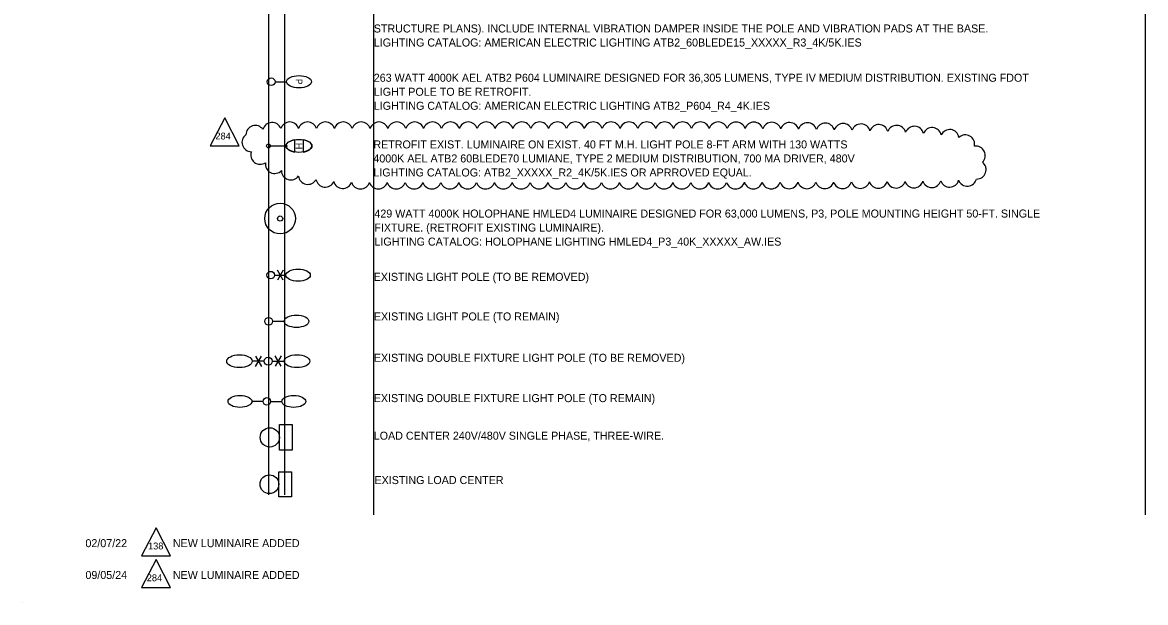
# Model space of a CAD drawing. Extents: x -0.6 to 15.1, y -0.9 to 9.2.
# Drawn here: x -0.55 to 9.27, y -0.9 to 4.17 of the extents above; entities that cross this region are included whole.
import ezdxf

# ---------------------------------------------------------------- set-up
doc = ezdxf.new("R2010")
doc.units = 0
for name, color, linetype in [('ActivePointCell_dp', 7, 'Continuous'), ('AdhocPoint_dp', 7, 'Continuous'), ('Cloud_dp', 7, 'Continuous'), ('LoadCenter', 7, 'Continuous'), ('LoadCenter_ep', 7, 'Continuous'), ('PoleLight', 7, 'Continuous'), ('PoleLight_ep', 7, 'Continuous'), ('TextLabel', 7, 'Continuous'), ('TextMisc', 7, 'Continuous')]:
    doc.layers.add(name, color=color, linetype=linetype)

msp = doc.modelspace()

# ---------------------------------------------------------------- linework, layer by layer
at = {"layer": 'ActivePointCell_dp'}
for p, q in [((2.5213, -0.1347), (2.5213, 8.8406)), ((9.2686, -0.1347), (9.2686, 8.9112)), ((1.7419, 8.8041), (1.7419, 0.0422)), ((1.6003, 8.6424), (1.6003, 0.0422))]:
    msp.add_line(p, q, dxfattribs=at)
at = {"layer": 'AdhocPoint_dp'}
msp.add_line((-0.55, -0.9), (-0.55, -0.9), dxfattribs=at)
at = {"layer": 'Cloud_dp'}
for points in [[(1.2182, 3.3362), (1.0915, 3.0921), (1.3449, 3.0921)], [(0.618, -0.2467), (0.4913, -0.4908), (0.7447, -0.4908)], [(0.618, -0.5247), (0.4913, -0.7688), (0.7447, -0.7688)]]:
    msp.add_lwpolyline(points, close=True, dxfattribs=at)
for centre, radius, start, end in [((1.4851, 3.188), 0.0818, 34.39181, 179.39181), ((1.6319, 3.2139), 0.0818, 20.63705, 165.63705), ((1.7865, 3.2181), 0.0818, 17.50167, 162.50167), ((1.9426, 3.2182), 0.0818, 17.5, 162.5), ((2.0987, 3.2182), 0.0818, 17.5, 162.5), ((2.2548, 3.2182), 0.0818, 17.5, 162.5), ((2.4109, 3.2182), 0.0818, 17.5, 162.5), ((2.567, 3.2182), 0.0818, 17.5, 162.5), ((2.7231, 3.2182), 0.0818, 17.50775, 162.50775), ((2.8792, 3.2182), 0.0818, 17.51566, 162.51566), ((3.0353, 3.2182), 0.0818, 17.51566, 162.51566), ((3.1914, 3.2183), 0.0818, 17.51566, 162.51566), ((3.3475, 3.2183), 0.0818, 17.51566, 162.51566), ((3.5036, 3.2184), 0.0818, 17.51566, 162.51566), ((3.6597, 3.2184), 0.0818, 17.51566, 162.51566), ((3.8158, 3.2184), 0.0818, 17.51566, 162.51566), ((3.9719, 3.2185), 0.0818, 17.51566, 162.51566), ((4.128, 3.2185), 0.0818, 17.51566, 162.51566), ((4.2841, 3.2186), 0.0818, 17.51566, 162.51566), ((4.4402, 3.2186), 0.0818, 17.51566, 162.51566), ((4.5963, 3.2187), 0.0818, 17.51566, 162.51566), ((4.7524, 3.2187), 0.0818, 17.51566, 162.51566), ((4.9085, 3.2187), 0.0818, 17.51566, 162.51566), ((5.0646, 3.2188), 0.0818, 17.51566, 162.51566), ((5.2207, 3.2188), 0.0818, 17.48665, 162.48665), ((5.3767, 3.2186), 0.0818, 17.39887, 162.39887), ((5.5328, 3.2182), 0.0818, 17.30058, 162.30058), ((5.6889, 3.2175), 0.0818, 17.19123, 162.19123), ((5.8449, 3.2165), 0.0818, 17.06859, 162.06859), ((6.0009, 3.2152), 0.0818, 16.92972, 161.92972), ((6.1569, 3.2134), 0.0818, 16.7707, 161.7707), ((6.3129, 3.2112), 0.0818, 16.58612, 161.58612), ((6.4689, 3.2084), 0.0818, 16.36832, 161.36832), ((6.6249, 3.2049), 0.0818, 16.10595, 161.10595), ((6.7808, 3.2007), 0.0818, 15.78139, 160.78139), ((6.9366, 3.1955), 0.0818, 15.36536, 160.36536), ((7.0923, 3.1889), 0.0818, 14.80475, 159.80475), ((7.2478, 3.1805), 0.0818, 13.98964, 158.98964), ((7.4029, 3.1691), 0.0818, 12.63875, 157.63875), ((1.4508, 3.1222), 0.0818, 125.49589, 270.49589), ((7.5567, 3.152), 0.0818, 9.63548, 154.63548), ((7.6929, 3.1055), 0.0818, 347.67382, 132.67382), ((7.7857, 3.0072), 0.0818, 314.04105, 99.04105), ((1.5281, 3.0117), 0.0818, 159.4718, 304.4718), ((7.7933, 2.8832), 0.0818, 267.88977, 52.88977), ((1.6553, 2.9318), 0.0818, 171.23593, 316.23593), ((1.7963, 2.875), 0.0818, 179.859, 324.859), ((1.9446, 2.8365), 0.0818, 186.09327, 331.09327), ((2.0965, 2.8126), 0.0818, 191.00451, 336.00451), ((2.2503, 2.8005), 0.0818, 195.00672, 340.00672), ((2.4053, 2.797), 0.0818, 197.41514, 342.41514), ((2.5614, 2.7969), 0.0818, 197.5, 342.5), ((2.7175, 2.7969), 0.0818, 197.5, 342.5), ((2.8736, 2.7969), 0.0818, 197.5, 342.5), ((3.0297, 2.7969), 0.0818, 197.5, 342.5), ((3.1858, 2.7969), 0.0818, 197.5, 342.5), ((3.3419, 2.7969), 0.0818, 197.5, 342.5), ((3.498, 2.7969), 0.0818, 197.5, 342.5), ((3.6541, 2.7969), 0.0818, 197.5, 342.5), ((3.8102, 2.7969), 0.0818, 197.5, 342.5), ((3.9663, 2.7969), 0.0818, 197.5, 342.5), ((4.1224, 2.7969), 0.0818, 197.5, 342.5), ((4.2785, 2.7969), 0.0818, 197.5, 342.5), ((4.4346, 2.7969), 0.0818, 197.5, 342.5), ((4.5907, 2.7969), 0.0818, 197.5, 342.5), ((4.7468, 2.7969), 0.0818, 197.5, 342.5), ((4.9029, 2.7969), 0.0818, 197.5, 342.5), ((5.059, 2.7969), 0.0818, 197.5, 342.5), ((5.2151, 2.7969), 0.0818, 197.50354, 342.50354), ((5.3711, 2.797), 0.0818, 197.52374, 342.52374), ((5.5272, 2.797), 0.0818, 197.54802, 342.54802), ((5.6833, 2.7972), 0.0818, 197.57496, 342.57496), ((5.8394, 2.7975), 0.0818, 197.60506, 342.60506), ((5.9955, 2.7978), 0.0818, 197.63901, 342.63901), ((6.1516, 2.7982), 0.0818, 197.67771, 342.67771), ((6.3076, 2.7988), 0.0818, 197.72236, 342.72236), ((6.4637, 2.7994), 0.0818, 197.77468, 342.77468), ((6.6198, 2.8003), 0.0818, 197.83715, 342.83715), ((6.7759, 2.8013), 0.0818, 197.91355, 342.91355), ((6.9319, 2.8026), 0.0818, 198.00998, 343.00998), ((7.0879, 2.8041), 0.0818, 198.13712, 343.13712), ((7.2439, 2.8061), 0.0818, 198.31582, 343.31582), ((7.3999, 2.8087), 0.0818, 198.5947, 343.5947), ((7.5557, 2.8124), 0.0818, 199.12998, 344.12998), ((7.7105, 2.8203), 0.0819, 201.69734, 346.69734)]:
    msp.add_arc(centre, radius, start, end, dxfattribs=at)
at = {"layer": 'LoadCenter'}
for p, q in [((1.6966, 0.431), (1.6966, 0.6559)), ((1.6966, 0.6559), (1.8091, 0.6559)), ((1.8091, 0.6559), (1.8091, 0.431)), ((1.8091, 0.431), (1.6966, 0.431))]:
    msp.add_line(p, q, dxfattribs=at)
msp.add_circle((1.6123, 0.5435), 0.0843, dxfattribs=at)
at = {"layer": 'LoadCenter_ep'}
for p, q in [((1.6911, 0.0243), (1.6911, 0.2436)), ((1.6911, 0.2436), (1.8008, 0.2436)), ((1.8008, 0.2436), (1.8008, 0.0243)), ((1.8008, 0.0243), (1.6911, 0.0243))]:
    msp.add_line(p, q, dxfattribs=at)
msp.add_circle((1.6089, 0.1339), 0.0822, dxfattribs=at)
at = {"layer": 'PoleLight'}
for p, q in [((1.6584, 3.6517), (1.7598, 3.6517)), ((1.8317, 3.0369), (1.8317, 3.1443)), ((1.9032, 3.1443), (1.9032, 3.0369)), ((1.5968, 3.0906), (1.7658, 3.0906))]:
    msp.add_line(p, q, dxfattribs=at)
for centre, radius in [((1.6246, 3.6517), 0.0338), ((1.6001, 3.0903), 0.0163), ((1.7026, 2.4559), 0.1344), ((1.7026, 2.4559), 0.0224)]:
    msp.add_circle(centre, radius, dxfattribs=at)
for centre, major_axis in [((1.8679, 3.6517), (0.1082, 0)), ((1.8674, 3.0906), (-0.1133, 0))]:
    msp.add_ellipse(centre, major_axis=major_axis, ratio=0.5, dxfattribs=at)
for start_param, end_param in [(5.033538, 6.283185), (1.891945, 4.391241), (0, 0.847605), (0.847605, 1.249648)]:
    msp.add_ellipse((1.8674, 3.0906), major_axis=(-0.1133, 0), ratio=0.5, start_param=start_param, end_param=end_param, dxfattribs=at)
at = {"layer": 'PoleLight_ep'}
for p, q in [((1.7285, 1.918), (1.6785, 2.0045)), ((1.7285, 2.0045), (1.6785, 1.918)), ((1.6535, 1.9613), (1.7534, 1.9613)), ((1.6363, 1.558), (1.7377, 1.558)), ((1.5636, 1.2092), (1.4589, 1.2092)), ((1.4861, 1.1633), (1.5385, 1.254)), ((1.4861, 1.254), (1.5385, 1.1633)), ((1.6334, 1.2092), (1.7381, 1.2092)), ((1.7109, 1.2551), (1.6586, 1.1645)), ((1.7109, 1.1645), (1.6586, 1.2551)), ((1.5539, 0.858), (1.456, 0.858)), ((1.6192, 0.858), (1.7171, 0.858))]:
    msp.add_line(p, q, dxfattribs=at)
for centre, radius in [((1.6202, 1.9613), 0.0333), ((1.6025, 1.558), 0.0338), ((1.5985, 1.2092), 0.0349), ((1.5866, 0.858), 0.0326)]:
    msp.add_circle(centre, radius, dxfattribs=at)
for centre, major_axis in [((1.86, 1.9613), (0.1066, 0)), ((1.8458, 1.558), (0.1082, 0)), ((1.3472, 1.2092), (-0.1117, 0)), ((1.8499, 1.2092), (0.1117, 0)), ((1.3515, 0.858), (-0.1045, 0)), ((1.8216, 0.858), (0.1045, 0))]:
    msp.add_ellipse(centre, major_axis=major_axis, ratio=0.5, dxfattribs=at)

# ---------------------------------------------------------------- texts
at = {"layer": 'Cloud_dp'}
for s, p in [('284', (1.1371, 3.1471)), ('138', (0.5481, -0.4358)), ('284', (0.5369, -0.7138))]:
    msp.add_text(s, height=0.05998, rotation=0, dxfattribs=at).set_placement(p)
at = {"layer": 'TextLabel'}
for s, p in [('P', (1.8393, 3.6775)), ('H', (1.8388, 3.1167))]:
    msp.add_text(s, height=0.0572, rotation=270.00003, dxfattribs=at).set_placement(p)
at = {"layer": 'TextMisc'}
for s, p in [('STRUCTURE PLANS). INCLUDE INTERNAL VIBRATION DAMPER INSIDE THE POLE AND VIBRATION PADS AT THE BASE.', (2.5213, 4.0821)), ('LIGHTING CATALOG: AMERICAN ELECTRIC LIGHTING ATB2_60BLEDE15_XXXXX_R3_4K/5K.IES', (2.5213, 3.9596)), ('263 WATT 4000K AEL ATB2 P604 LUMINAIRE DESIGNED FOR 36,305 LUMENS, TYPE IV MEDIUM DISTRIBUTION. EXISTING FDOT ', (2.5213, 3.6516)), ('LIGHT POLE TO BE RETROFIT.', (2.5213, 3.5291)), ('LIGHTING CATALOG: AMERICAN ELECTRIC LIGHTING ATB2_P604_R4_4K.IES', (2.5213, 3.4066)), ('RETROFIT EXIST. LUMINAIRE ON EXIST. 40 FT M.H. LIGHT POLE 8-FT ARM WITH 130 WATTS', (2.5178, 3.0688)), ('4000K AEL ATB2 60BLEDE70 LUMIANE, TYPE 2 MEDIUM DISTRIBUTION, 700 MA DRIVER, 480V', (2.5178, 2.9463)), ('LIGHTING CATALOG: ATB2_XXXXX_R2_4K/5K.IES OR APRROVED EQUAL.', (2.5178, 2.8238)), ('429 WATT 4000K HOLOPHANE HMLED4 LUMINAIRE DESIGNED FOR 63,000 LUMENS, P3, POLE MOUNTING HEIGHT 50-FT. SINGLE ', (2.5267, 2.4646)), ('FIXTURE. (RETROFIT EXISTING LUMINAIRE).', (2.5267, 2.3421)), ('LIGHTING CATALOG: HOLOPHANE LIGHTING HMLED4_P3_40K_XXXXX_AW.IES', (2.5267, 2.2196))]:
    msp.add_text(s, height=0.07, dxfattribs=at).set_placement(p)
for s, p in [('EXISTING LIGHT POLE (TO BE REMOVED)', (2.5203, 1.9116)), ('EXISTING LIGHT POLE (TO REMAIN)', (2.5222, 1.5653)), ('EXISTING DOUBLE FIXTURE LIGHT POLE (TO BE REMOVED)', (2.5218, 1.2038)), ('EXISTING DOUBLE FIXTURE LIGHT POLE (TO REMAIN)', (2.5213, 0.8516)), ('LOAD CENTER 240V/480V SINGLE PHASE, THREE-WIRE.', (2.5213, 0.5232)), ('EXISTING LOAD CENTER', (2.5276, 0.1353)), ('02/07/22', (0.0005, -0.4161)), ('NEW LUMINAIRE ADDED', (0.765, -0.4161)), ('09/05/24', (0.0005, -0.6941)), ('NEW LUMINAIRE ADDED', (0.765, -0.6941))]:
    msp.add_text(s, height=0.07, rotation=360, dxfattribs=at).set_placement(p)

doc.saveas('drawing.dxf')
